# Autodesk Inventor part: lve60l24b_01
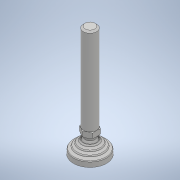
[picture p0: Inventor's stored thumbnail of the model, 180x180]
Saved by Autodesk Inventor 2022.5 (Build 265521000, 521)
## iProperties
Part Number: lve60l24b_01
Material: 一般
Document SubType Name: Modeling
Designer: ImaoCorp
Density: 1 g/cm^3
Appearance: 既定
Author: ImaoCorp
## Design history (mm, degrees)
feature "lve60l24b_01"
node "ソリッド1"
